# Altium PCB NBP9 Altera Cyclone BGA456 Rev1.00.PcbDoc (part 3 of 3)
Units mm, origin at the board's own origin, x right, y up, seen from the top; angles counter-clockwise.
Board outline 69 x 80.99 mm, 6 copper layers (Top Layer, MidLayer1, InternalPlane1, InternalPlane2, MidLayer2, Bottom Layer); 105 components, 269 nets, 899 pads, 453 vias.
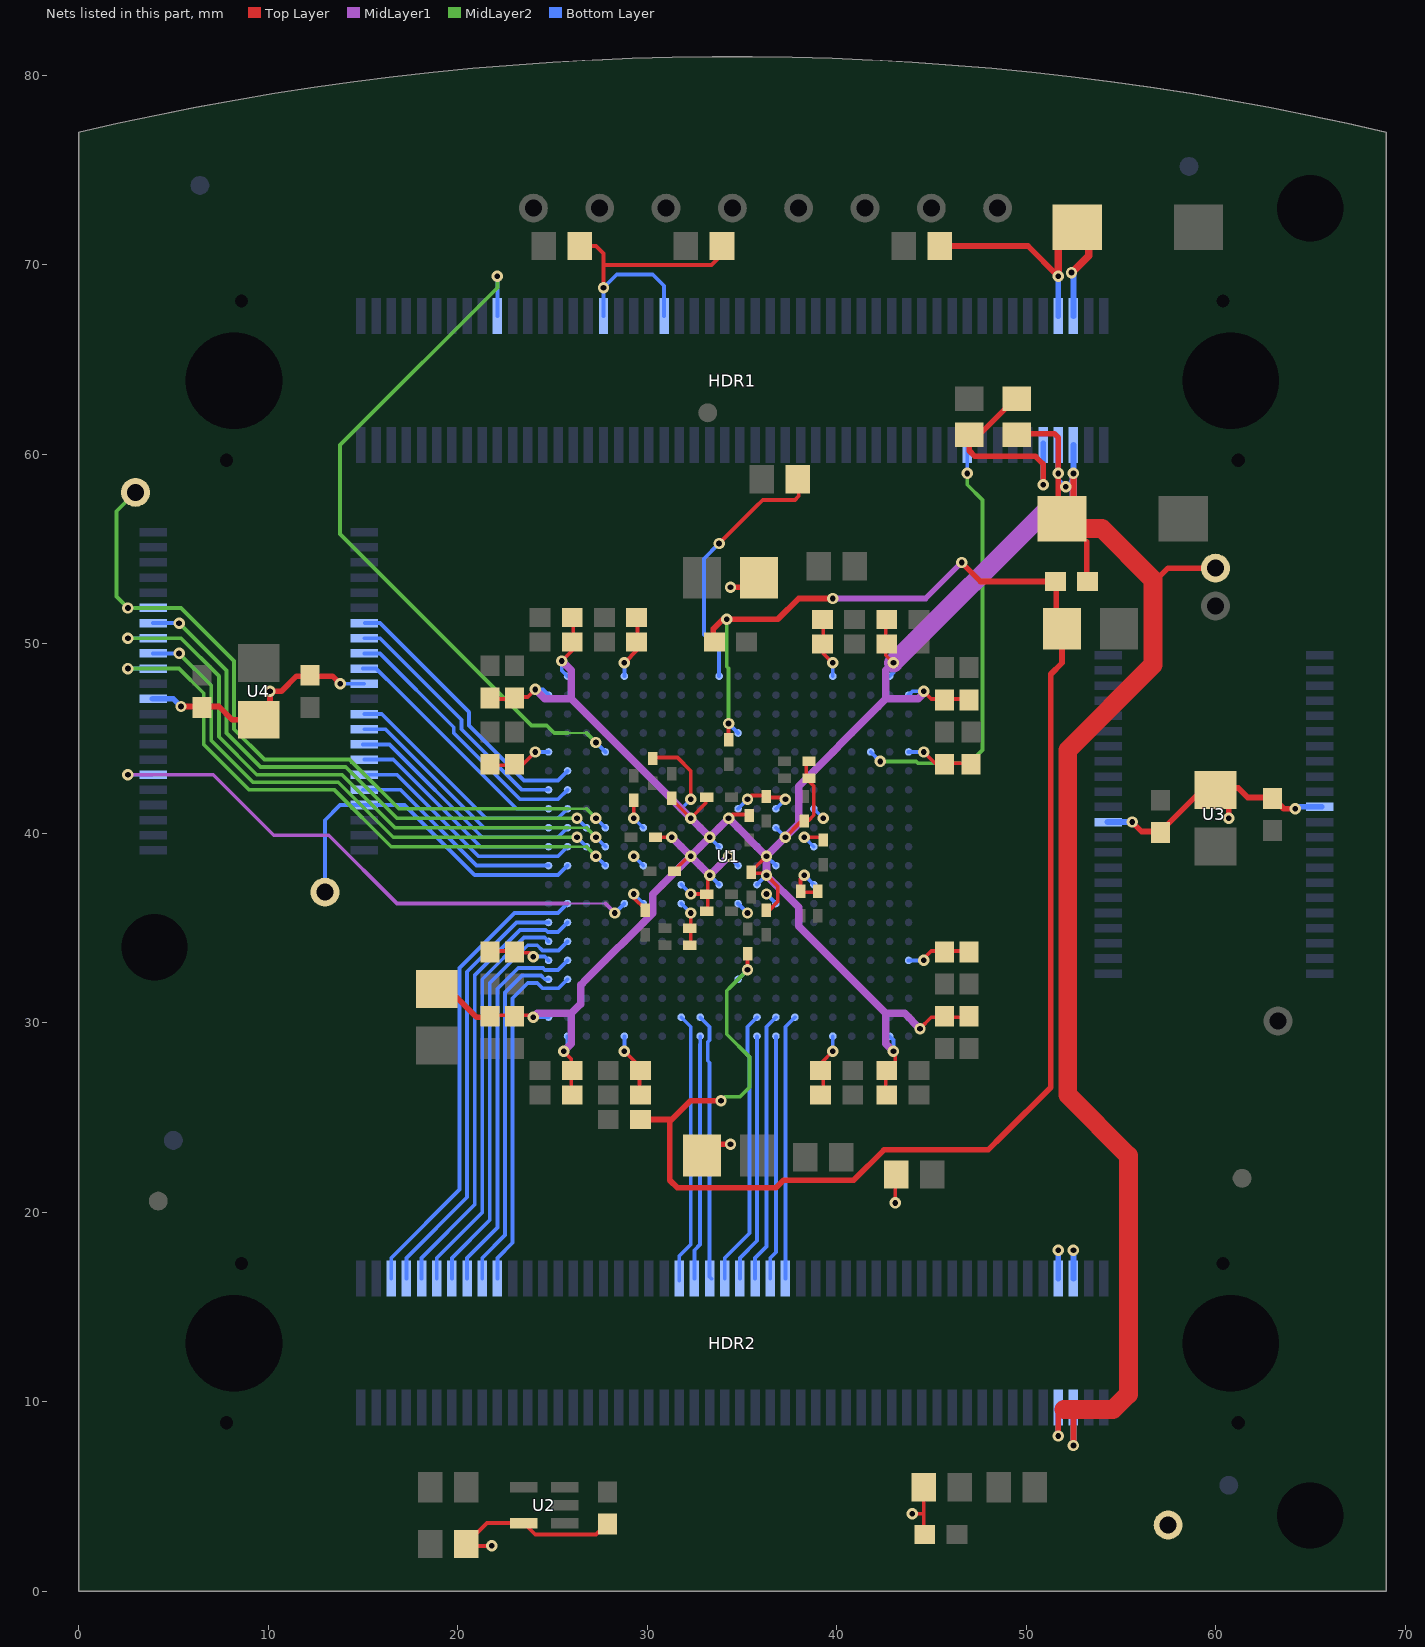
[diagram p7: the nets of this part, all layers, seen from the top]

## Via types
v1: diameter 0.6, hole 0.3, Top Layer to Bottom Layer, 453 vias

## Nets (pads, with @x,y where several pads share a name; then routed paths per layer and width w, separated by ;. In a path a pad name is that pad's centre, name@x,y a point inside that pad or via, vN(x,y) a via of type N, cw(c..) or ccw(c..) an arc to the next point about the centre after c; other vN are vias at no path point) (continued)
SRAM1_D4: U1.U10 U4.13 | length 32.4
  MidLayer2 w0.127: 25.8,39.3 26.8,39.3
  MidLayer2 w0.2: v1(2.6,48.7) 5.3,48.7 6.6,47.4 6.6,44.7 9,42.3 13.5,42.3 16.5,39.3 25.8,39.3 ; 26.8,39.3 v1(27.3,38.8)
  Bottom Layer w0.2: v1(2.6,48.7) U4.13@3.925,48.7 ; v1(27.3,38.8) U1.U10@27.8,38.3
SRAM1_D5: U1.V11 U4.14 | length 28.8
  MidLayer2 w0.2: v1(5.3,49.5) 7,47.8 7,44.9 9.2,42.7 13.7,42.7 16.6,39.8 v1(26.3,39.8)
  Bottom Layer w0.2: U4.14@3.925,49.5 v1(5.3,49.5) ; v1(26.3,39.8) U1.V11@26.8,39.3
SRAM1_D6: U1.U11 U4.15 | length 33.2
  MidLayer2 w0.127: 25.8,40.3 26.8,40.3
  MidLayer2 w0.2: v1(2.6,50.3) 5.4,50.3 7.4,48.3 7.4,45.1 9.4,43.1 13.9,43.1 16.7,40.3 25.8,40.3 ; 26.8,40.3 v1(27.3,39.8)
  Bottom Layer w0.2: v1(2.6,50.3) U4.15@3.9,50.3 ; v1@27.5,39.6 v1(27.3,39.8) U1.U11@27.8,39.3
SRAM1_D7: U1.V12 U4.16 | length 29.6
  MidLayer2 w0.2: v1(5.3,51.1) 7.8,48.6 7.8,45.3 9.6,43.5 14.1,43.5 16.8,40.8 v1(26.3,40.8)
  Bottom Layer w0.2: U4.16@3.925,51.1 v1(5.3,51.1) ; v1@26.5,40.6 v1(26.3,40.8) U1.V12@26.8,40.3
SRAM1_D8: U1.W15 U4.29 | length 14.8
  Bottom Layer w0.2: U4.29@15.1,51.1 15.9,51.1 20.6,46.4 20.6,45.7 23.5,42.8 25.3,42.8 U1.W15@25.8,43.3
SRAM1_D9: U1.Y14 U4.30 | length 13.3
  Bottom Layer w0.2: U4.30@15.075,50.3 15.9,50.3 20.2,46 20.2,45.5 23.4,42.3 24.375,42.3 ; 24.4,42.3 U1.Y14@24.8,42.3
SRAM1_D10: U1.W14 U4.31 | length 14.3
  Bottom Layer w0.2: U4.31@15.075,49.5 15.9,49.5 19.8,45.6 19.8,45.3 23.3,41.8 25.3,41.8 U1.W14@25.8,42.3
SRAM1_D11: U1.Y13 U4.32 | length 12.8
  Bottom Layer w0.2: U4.32@15,48.7 15.7,48.7 16.9,47.5 23.1,41.3 24.375,41.3 ; 24.4,41.3 U1.Y13@24.8,41.3
SRAM1_D12: U1.W13 U4.35 | length 13.2
  Bottom Layer w0.2: U4.35@15.075,46.3 16,46.3 21,41.3 21.5,40.8 25.3,40.8 25.499,41 U1.W13@25.8,41.3
SRAM1_D13: U1.Y12 U4.36 | length 11.9
  Bottom Layer w0.2: U4.36@15.075,45.5 16.2,45.5 21.4,40.3 24.375,40.3 ; 24.4,40.3 U1.Y12@24.8,40.3
SRAM1_D14: U1.W12 U4.37 | length 13
  Bottom Layer w0.2: U4.37@15,44.7 16.4,44.7 21.3,39.8 25.3,39.8 U1.W12@25.8,40.3
SRAM1_D15: U1.Y11 U4.38 | length 11.6
  Bottom Layer w0.2: U4.38@15.075,43.9 16.6,43.9 21.2,39.3 U1.Y11@24.8,39.3
SRAM1_E: U1.T8 U4.6 | length 30.7
  MidLayer1 w0.127: 25.8,36.3 27.8,36.3
  MidLayer1 w0.2: v1(2.6,43.1) 7.1,43.1 10.3,39.9 13.2,39.9 16.8,36.3 25.8,36.3 ; 27.8,36.3 v1(28.3,35.8)
  Bottom Layer w0.2: v1(2.6,43.1) U4.6@3.9,43.1 ; v1(28.3,35.8) U1.T8@28.8,36.3
SRAM1_LB: U1.W11 U4.39 | length 12.7
  Bottom Layer w0.2: U4.39@15.075,43.1 16.8,43.1 21.1,38.8 25.3,38.8 U1.W11@25.8,39.3
SRAM1_OE: TP2.1 U1.W10 U4.41 | length 18.7
  Bottom Layer w0.2: TP2.1@13,36.9 13,40.7 13.8,41.5 17.2,41.5 20.9,37.8 25.3,37.8 U1.W10@25.8,38.3
SRAM1_UB: U1.Y10 U4.40 | length 11.4
  Bottom Layer w0.2: U4.40@15,42.3 17,42.3 21,38.3 24.375,38.3 ; 24.4,38.3 U1.Y10@24.8,38.3
SRAM1_W: TP5.1 U1.U12 U4.17 | length 40.5
  MidLayer2 w0.127: 25.8,41.3 26.8,41.3
  MidLayer2 w0.2: TP5.1@3,58 2,57 2,52.5 v1(2.6,51.9) 5.4,51.9 8.2,49.1 8.2,45.5 9.8,43.9 14.3,43.9 16.9,41.3 25.8,41.3 ; 26.8,41.3 v1(27.3,40.8)
  Bottom Layer w0.2: v1(2.6,51.9) U4.17@3.9,51.9 ; v1@27.5,40.6 v1(27.3,40.8) U1.U12@27.8,40.3
SW0: HDR2.44 U1.N2 | length 14.4
  Bottom Layer w0.2: HDR2.44@31.7,16.4 31.7,17.7 32.3,18.3 32.3,29.8 U1.N2@31.8,30.3
SW1: HDR2.46 U1.M1 | length 13
  Bottom Layer w0.2: HDR2.46@32.5,16.5 32.5,18 32.8,18.3 32.8,28.875 ; 32.8,28.8 U1.M1@32.8,29.3
SW2: HDR2.48 U1.M2 | length 14.1
  Bottom Layer w0.2: U1.M2@32.8,30.3 33.3,29.8 33.3,29.1 33.2,29 33.2,28 33.3,27.9 33.3,16.6 33.35,16.55 HDR2.48@33.4,16.5
SW3: HDR2.50 U1.J2 | length 14.6
  Bottom Layer w0.2: HDR2.50@34.1,16.5 34.1,17.6 35.4,18.9 35.4,28.2 35.3,28.3 35.3,29.8 U1.J2@35.8,30.3
SW4: HDR2.52 U1.J1 | length 13.1
  Bottom Layer w0.2: HDR2.52@34.9,16.5 34.9,17.6 35.8,18.5 35.8,28.875 ; 35.8,28.9 U1.J1@35.8,29.3
SW5: HDR2.54 U1.H2 | length 14.3
  Bottom Layer w0.2: HDR2.54@35.7,16.5 35.7,17.6 36.3,18.2 36.3,29.8 U1.H2@36.8,30.3
SW6: HDR2.56 U1.H1 | length 13
  Bottom Layer w0.2: HDR2.56@36.5,16.5 36.5,17.6 36.8,17.9 36.8,28.875 ; 36.8,28.8 U1.H1@36.8,29.3
SW7: HDR2.58 U1.G2 | length 14
  Bottom Layer w0.2: HDR2.58@37.3,16.5 37.3,17.6 37.3,29.8 U1.G2@37.8,30.3
SWC0: HDR2.18 U1.Y4 | length 18.4
  Bottom Layer w0.2: HDR2.18@21.3,16.5 21.3,17.6 22.5,18.8 22.5,31.6 23.4,32.5 24.4,32.5 24.6,32.3 U1.Y4@24.8,32.3
SWC1: HDR2.16 U1.W5 | length 20.4
  Bottom Layer w0.2: HDR2.16@20.5,16.5 20.5,17.6 22.1,19.2 22.1,31.8 23.2,32.9 24.5,32.9 24.6,32.8 25.3,32.8 U1.W5@25.8,33.3
SWC2: HDR2.14 U1.W6 | length 21.7
  Bottom Layer w0.2: HDR2.14@19.7,16.5 19.7,17.6 21.7,19.6 21.7,32.1 23.7,34.1 24.2,34.1 24.475,33.825 25.325,33.825 U1.W6@25.8,34.3
SWC3: HDR2.6 U1.W8 | length 25
  Bottom Layer w0.2: HDR2.6@16.5,16.5 16.5,17.6 20.1,21.2 20.1,32.9 23,35.8 25.3,35.8 U1.W8@25.8,36.3
SWR0: HDR2.20 U1.W4 | length 18.7
  Bottom Layer w0.2: HDR2.20@22.1,16.5 22.1,17.6 22.9,18.4 22.9,31.3 23.7,32.1 24.2,32.1 24.475,31.825 25.325,31.825 U1.W4@25.8,32.3
SWR1: HDR2.12 U1.Y6 | length 21.3
  Bottom Layer w0.2: HDR2.12@18.9,16.5 18.9,17.6 21.3,20 21.3,32.3 23.5,34.5 24.6,34.5 U1.Y6@24.8,34.3
SWR2: HDR2.10 U1.W7 | length 23.3
  Bottom Layer w0.2: HDR2.10@18.1,16.5 18.1,17.6 20.9,20.4 20.9,32.5 23.3,34.9 24.656,34.9 24.756,34.8 25.3,34.8 U1.W7@25.8,35.3
SWR3: HDR2.8 U1.Y7 | length 22.9
  Bottom Layer w0.2: HDR2.8@17.3,16.5 17.3,17.6 20.5,20.8 20.5,32.7 23.1,35.3 24.375,35.3 ; 24.4,35.3 U1.Y7@24.8,35.3
TDO: R7.2 U1.L20 | length 15.7
  Top Layer w0.2: 35,56.5 v1(33.8,55.3) 35.7,57.2 36.1,57.6 37.8,57.6 38,57.8 R7.2@38,58.8
  Bottom Layer w0.2: U1.L20@33.8,48.3 33.8,49.7 33,50.5 33,54.5 v1(33.8,55.3) v1@33.8,55.4
TEST: HDR1.81 U1.C16 | length 23.2
  MidLayer2 w0.2: v1(42.3,43.8) 44.2,43.8 44.3,43.7 47,43.7 47.7,44.4 47.7,57.6 46.9,58.4 v1(46.9,59)
  Bottom Layer w0.2: U1.C16@41.8,44.3 v1(42.3,43.8) v1@42.101,43.999 ; v1(46.9,59) HDR1.81@46.9,60.5
VCC: C2.1 C3.1 C4.1 C5.1 C9.1 C10.1 C11.1 C12.1 C13.1 C14.1 C15.1 C16.1 C17.2 C28.1 C29.1 C30.1 C31.1 C32.1 C33.1 C34.1 C35.1 C36.1 C37.1 C38.1 C39.1 C40.1 C41.1 C42.1 C43.1 C44.1 C45.1 C46.1 C47.1 C48.1 C49.1 C51.1 HDR1.34 HDR1.42 HDR1.94 HDR1.96 HDR2.94 HDR2.96 R1.1 R2.1 R3.1 R10.1 R11.2 R12.2 TP3.1 U1.A5 U1.A16 U1.E1 U1.E20 U1.F9 U1.F11 U1.F13 U1.H8 U1.H13 U1.K8 U1.K13 U1.N8 U1.N13 U1.R8 U1.R10 U1.R12 U1.T1 U1.T20 U1.Y5 U1.Y16 U2.5 U3.11 U3.33 U4.11 U4.33 | length 133.1
  Top Layer w0.2: R11.2@20.45,2.5 21.55,3.6 U2.5@23.5,3.6 24.1,3 27.3,3 C17.2@27.9,3.6 ; R11.2@20.5,2.4 v1(21.8,2.4) ; C9.1@21.7,33.8 C34.1@23,33.8 ; C32.1@21.7,43.7 21.8,43.6 23,43.6 23.4,43.6 v1(24.1,44.3) ; C34.1@23,33.7 23.8,33.7 v1(24,33.5) ; R3.1@26.4,71 27.3,71 27.7,70.6 v1(27.7,68.8) ; 27.7,70 33.4,70 33.9,70.5 R2.1@33.9,71.1 ; v1@28.7,28.4 v1(28.8,28.5) 29.7,27.6 C41.1@29.7,27.5 ; v1@28.7,49.1 v1(28.8,49) 29.5,49.7 29.5,51.3 C15.1@29.2,51.6 ; v1(29.3,36.8) 29.3,36.6 C30.1@29.9,36 ; v1(29.3,40.8) C38.1@29.3,41.8 ; C37.1@29.6,26.2 C41.1@29.6,27.6 ; C31.1@30.2,44 31.6,44 32.3,43.3 v1(32.3,41.8) ; C13.1@32.3,34.1 v1(32.3,35.8) ; v1(35.3,41.8) 35.5,42 C36.1@36.3,42 ; C2.1@35.9,53.6 C2.1@36,53.6 ; C36.1@36.3,41.9 37.2,41.9 v1(37.3,41.8) ; v1(38.3,39.8) C44.1@39.3,39.8 ; v1@38.4,37.7 v1(38.3,37.8) 38.1,37.6 38.1,36.9 C47.1@39,36.9 ; C16.1@39.3,26.2 39.3,27.3 39.2,27.4 39.2,27.9 v1(39.8,28.5) v1@39.9,28.4 ; C33.1@39.3,50 39.3,49.5 v1(39.8,49) ; C33.1@39.3,50.1 C14.1@39.3,51.3 ; v1(43.1,20.5) R12.2@43.1,22 ; v1(44,4.1) 44.6,4.1 ; v1@44.5,33.3 45,33.8 C43.1@47,33.8 ; C29.1@44.6,2.9 R10.1@44.6,5.5 ; v1(44.6,44.3) 45.2,43.7 45.7,43.7 C11.1@47.1,43.7
  Top Layer w0.3: v1(5.4,46.7) 7.4,46.7 8.1,46 C4.1@9.5,46 10.1,46.6 v1(10.1,47.5) 10.7,47.5 11.5,48.3 13.4,48.3 v1(13.8,47.9) ; C3.1@32.8,23.6 v1(34.4,23.6) ; v1(34.4,53) 35.4,53 C2.1@35.9,53.5 ; R1.1@45.4,71 50.1,71 v1(51.7,69.4) ; v1(55.6,40.6) 56.1,40.1 57.1,40.1 59.4,42.4 61.2,42.4 61.7,41.9 63,41.9 63.6,41.3 v1(64.2,41.3) ; C5.1@60,42.4 60.7,41.7 v1(60.7,40.8)
  Top Layer w0.4: v1(51.7,69.4) 51.7,71.8 51.9,72 C51.1@53.3,72 ; v1(52.4,69.6) 53.3,70.5 C51.1@53.3,71.9
  Bottom Layer w0.2: v1(13.8,47.9) U4.33@15.075,47.9 ; v1(24,33.5) 24.6,33.5 U1.Y5@24.8,33.3 ; v1(24.1,44.3) U1.Y16@24.8,44.3 ; HDR1.34@27.7,67.3 v1(27.7,68.8) 28.4,69.5 30.3,69.5 30.9,68.9 HDR1.42@30.9,67.3 ; v1@28.8,28.6 U1.T1@28.8,29.3 ; U1.T20@28.8,48.3 v1(28.8,49) ; v1(29.3,36.8) U1.R8@29.8,36.3 ; v1(29.3,38.8) U1.R10@29.8,38.3 ; v1(29.3,40.8) U1.R12@29.8,40.3 ; U1.N8@31.8,36.3 v1(32.3,35.8) ; U1.N13@31.8,41.3 v1(32.3,41.8) ; U1.K13@34.8,41.3 v1(35.3,41.8) ; U1.K8@34.8,36.3 v1(35.3,35.8) ; v1(36.3,36.8) U1.H8@36.8,36.3 ; U1.H13@36.8,41.3 v1(37.3,41.8) ; v1(38.3,37.8) U1.F9@38.8,37.3 ; v1(38.3,39.8) U1.F11@38.8,39.3 ; U1.F13@38.8,41.3 v1(39.3,40.8) ; v1@39.8,28.6 U1.E1@39.8,29.3 ; U1.E20@39.8,48.3 v1(39.8,49) ; U1.A5@43.8,33.3 v1@44.5,33.3 ; U1.A16@43.8,44.3 v1(44.6,44.3)
  Bottom Layer w0.3: U4.11@3.9,47.1 5,47.1 v1(5.4,46.7) ; HDR2.94@51.7,16.5 v1(51.7,18) ; HDR1.94@51.7,67.3 v1(51.7,69.4) ; v1@52.4,69.5 v1(52.4,69.6) ; HDR2.96@52.5,16.5 v1(52.5,18) ; HDR1.96@52.5,67.3 v1@52.5,69.5 ; U3.11@54.3,40.6 v1(55.6,40.6) ; v1(64.2,41.3) 64.3,41.4 U3.33@65.6,41.4
  other v1: 44.6,33.3 51.7,69.4
VCCA_PLL1: C6.1 C52.1 C53.1 C54.1 C55.1 L1.2 U1.K4 U1.K17 | length 95.6
  Top Layer w0.2: C54.1@34.3,45 v1(34.3,45.8) ; v1(35.3,32.8) C55.1@35.3,33.6
  Top Layer w0.3: C53.1@29.65,24.9 31.3,24.9 ; C52.1@33.5,50 33.5,50.8 34,51.3 36.9,51.3 38,52.4 v1(39.8,52.4) ; v1(33.9,25.9) 32.3,25.9 31.2,24.8 31.2,21.7 31.6,21.3 36.8,21.3 37.2,21.7 40.9,21.7 42.5,23.3 48,23.3 48.8,24.1 51.3,26.6 51.3,48.4 51.9,49 C6.1@51.9,50.8 ; v1(46.6,54.3) 47.6,53.3 51.6,53.3 51.6,51.3 C6.1@52,50.9
  MidLayer1 w0.3: v1(39.8,52.4) 44.7,52.4 v1(46.6,54.3)
  MidLayer2 w0.2: v1(33.9,25.9) 34.1,26.1 34.9,26.1 35.4,26.6 35.4,28.2 34.2,29.4 34.2,31.7 34.4,31.9 v1(35.3,32.8) ; v1(34.2,51.3) 34.2,50.7 34.2,48.8 34.3,48.7 v1(34.3,45.8)
  Bottom Layer w0.2: v1(34.3,45.8) U1.K17@34.8,45.3 ; U1.K4@34.8,32.3 v1(35.3,32.8)
VCCINT: C1.1 C7.1 C8.1 C18.1 C19.1 C20.1 C21.1 C22.1 C23.1 C24.1 C25.1 C26.1 C27.1 C50.1 C56.1 C57.1 C58.1 C59.1 C60.1 C61.1 C62.1 C63.1 C64.1 C65.1 C66.1 C67.1 C68.1 C69.1 C70.1 C71.1 HDR1.93 HDR1.95 HDR2.93 HDR2.95 L1.1 R8.1 TP6.1 U1.A2 U1.A19 U1.B1 U1.B20 U1.H10 U1.H12 U1.J9 U1.J11 U1.K10 U1.K12 U1.L9 U1.L11 U1.M10 U1.M12 U1.N9 U1.N11 U1.W1 U1.W20 U1.Y2 U1.Y19 | length 224.5
  Top Layer w0.2: C63.1@21.7,30.4 23.9,30.4 v1(24,30.3) ; C58.1@21.7,47.2 21.8,47.1 C67.1@23,47.1 ; C67.1@23,47.2 23.7,47.2 v1(24.1,47.6) ; v1(25.5,49.1) 26.1,49.7 26.1,51.3 C59.1@25.9,51.5 ; v1(25.6,28.5) 26,28.1 C57.1@26,26.3 ; C21.1@30.4,39.8 v1(31.3,39.8) ; C8.1@31.3,41.9 31.3,41.8 v1(32.3,40.8) 33.1,41.6 C24.1@33.1,41.8 ; C27.1@31.4,38 32.2,38.8 v1(32.3,38.8) ; v1(32.3,36.8) C7.1@33.2,36.8 ; C23.1@33.2,35.9 C7.1@33.2,36.8 ; v1(33.3,37.8) 33.2,37.7 C7.1@33.2,36.8 ; v1(34.3,40.8) 34.5,41 C20.1@35.3,41 ; C26.1@35.5,37.9 36.2,37.9 v1(36.3,37.8) 36.9,37.2 36.9,36.4 36.4,35.9 C22.1@36.3,35.9 ; C26.1@35.5,38 v1(36.3,38.8) ; v1(37.3,39.8) 38.1,40.6 C18.1@38.3,40.6 ; C18.1@38.2,40.7 38.54,40.7 38.8,40.96 38.8,42.5 38.4,42.9 C19.1@38.4,43.8 ; C62.1@42.6,26.2 C65.1@42.6,27.6 ; C56.1@42.7,51.4 42.6,51.3 42.6,49.4 v1(43,49) ; v1(43,28.5) 43.1,28.4 C65.1@43.1,27.5 ; v1(44.4,29.7) 45,30.3 C61.1@47,30.3 ; v1(44.6,47.5) 45,47.1 C60.1@47,47.1
  Top Layer w0.3: C1.1@18.9,31.8 19.5,31.8 21,30.3 C63.1@21.7,30.3 ; R8.1@49.5,61.1 51.5,61.1 51.7,60.9 C50.1@51.7,56.6 ; v1(51.7,8.2) 51.7,9.6 ; v1(52.5,7.7) 52.5,9.6 ; C50.1@52.5,57.2 v1(52.5,59) ; L1.1@53.2,53.3 53.2,55.4 ; 56.6,53.1 57.5,54 TP6.1@60,54
  Top Layer w1: C50.1@51.9,56.1 54,56.1 56.7,53.4 56.7,48.9 52.2,44.4 52.2,26.2 55.4,23 55.4,13.8 ; 52,9.6 54.6,9.6 55.4,10.4 55.4,14
  MidLayer1 w0.2: 51.7,58.7 v1(51.7,59)
  MidLayer1 w0.4: v1(24,30.3) 24.2,30.5 26,30.5 ; v1(24.1,47.6) 24.6,47.1 26,47.1 ; v1(25.5,49.1) 26,48.6 26,47.1 ; v1(25.6,28.5) 26,28.9 26,30.5 ; v1(31.3,39.8) v1(32.3,38.8) ; v1(34.3,38.8) v1(33.3,37.8) v1(32.3,38.8) ; v1(43,28.5) 42.6,28.9 42.6,30.5 ; v1(43,49) 42.6,48.6 42.6,47.1 ; v1(44.4,29.7) 43.6,30.5 42.6,30.5 ; v1@44.65,47.45 44.3,47.1 42.6,47.1 ; 52.5,57.3 v1(52.5,59) ; 26,30.5 26.5,31 26.5,32 26.8,32.3 30.3,35.8 30.3,36.8 v1(32.3,38.8) ; 26,47.1 v1(33.3,39.8) ; v1(32.3,38.8) v1(33.3,39.8) ; v1(33.3,39.8) v1(34.3,40.8) v1(36.3,38.8) ; v1(36.3,38.8) v1(36.3,37.8) 38,36.1 38,35.1 42.6,30.5 ; v1(36.3,38.8) v1(37.3,39.8) 38,40.5 38,42.5 42.2,46.7 42.6,47.1
  MidLayer1 w1: v1(43,49) 51.3,57.3 52.5,57.3
  Bottom Layer w0.2: v1(24,30.3) U1.Y2@24.8,30.3 ; v1(24.1,47.6) 24.5,47.6 U1.Y19@24.8,47.3 ; v1(25.5,49.1) 25.5,48.6 U1.W20@25.8,48.3 ; v1@25.65,28.45 25.8,28.6 U1.W1@25.8,29.3 ; v1(31.3,39.8) U1.N11@31.8,39.3 ; U1.N9@31.8,37.3 v1(32.3,36.8) ; v1(32.3,38.8) U1.M10@32.8,38.3 ; v1(32.3,40.8) U1.M12@32.8,40.3 ; v1(33.3,37.8) U1.L9@33.8,37.3 ; v1(33.3,39.8) U1.L11@33.8,39.3 ; v1(34.3,38.8) U1.K10@34.8,38.3 ; v1(34.3,40.8) U1.K12@34.8,40.3 ; U1.J9@35.8,37.3 v1(36.3,37.8) ; U1.J11@35.8,39.3 v1(36.3,38.8) U1.H10@36.8,38.3 ; U1.H12@36.8,40.3 v1(37.3,39.8) ; U1.B1@42.8,29.3 43,29.1 v1(43,28.5) ; U1.B20@42.8,48.3 43,48.5 v1(43,49) ; U1.A2@43.8,30.3 v1(44.4,29.7) ; U1.A19@43.8,47.3 44,47.5 v1(44.6,47.5) ; v1(51.7,59) 51.7,58.7 v1(52.1,58.3) 52.5,58.7 v1(52.5,59)
  Bottom Layer w0.3: v1(51.7,8.2) HDR2.93@51.7,9.7 ; v1(51.7,59) HDR1.93@51.7,60.5 ; v1(52.5,7.7) HDR2.95@52.5,9.7 ; v1(52.5,59) HDR1.95@52.5,60.5
VDRIVE: HDR1.20 U1.U16 | length 38.2
  MidLayer2 w0.127: 25.8,45.3 26.8,45.3
  MidLayer2 w0.2: v1(22.1,69.4) 22.1,68.8 14.3,61 13.8,60.5 13.8,55.8 23.9,45.7 24.7,45.7 25.1,45.3 25.8,45.3 ; 26.8,45.3 v1(27.3,44.8)
  Bottom Layer w0.2: HDR1.20@22.1,67.3 v1(22.1,69.4) ; v1@27.5,44.6 v1(27.3,44.8) U1.U16@27.8,44.3
VREF: HDR1.91 R8.2 R9.1 | length 11.7
  Top Layer w0.3: R8.2@49.5,63 49.475,62.975 47.6,61.1 47,61.1 47,60.2 47.3,59.9 50.5,59.9 50.9,59.5 v1(50.9,58.4)
  Bottom Layer w0.3: v1(50.9,58.4) HDR1.91@50.9,60.6
pads on no net: HDR1.MH1 HDR1.MH2 HDR1.MH3 HDR1.MH4 HDR1.MH5 HDR1.MH6 HDR2.MH1 HDR2.MH2 HDR2.MH3 HDR2.MH4 HDR2.MH5 HDR2.MH6 U1.B3 U1.C4 U1.C6 U1.D3 U1.D17 U1.D18 U1.E12 U1.E16 U1.F6 U1.F8 U1.F10 U1.F12 U1.F14 U1.F15 U1.G7 U1.G14 U1.G15 U1.H7 U1.H14 U1.H15 U1.J6 U1.J7 U1.J8 U1.J13 U1.J14 U1.J16 U1.K2 U1.K15 U1.K16 U1.K19 U1.L2 U1.L4 U1.L8 U1.L13 U1.M6 U1.M7 U1.M8 U1.M13 U1.M14 U1.M15 U1.N6 U1.N7 U1.N14 U1.N15 U1.P6 U1.P7 U1.P14 U1.P15 U1.P16 U1.R7 U1.R9 U1.R11 U1.R13 U1.R14 U1.R15 U1.R16 U1.V14 U2.1

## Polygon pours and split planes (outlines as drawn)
GND on Top Layer "Top Layer-GND" (solid, remove dead copper, pour order 1000): 0,0 0,82.9 69,82.9 69,0
VCCINT on MidLayer1 "MidLayer1-VCCINT" (solid, remove dead copper, pour order 1001): 0,0 0,82.7 69,82.7 69,0.1 0,0.1
VCC on MidLayer2 "MidLayer2-VCC" (solid, remove dead copper, pour order 1002): 0,0 0,83.4 69,83.4 69,0
GND on Bottom Layer "Bottom Layer-GND" (solid, remove dead copper, pour order 1003): 0,0 0,83.2 69,83.2 69,0
VCC on InternalPlane1 (split plane): 36.232,80.189 37.965,80.159 39.696,80.109 41.427,80.039 43.158,79.949 44.887,79.839 46.614,79.709 48.34,79.559 50.064,79.389 51.786,79.2 53.506,78.99 55.223,78.761 56.938,78.511 58.649,78.242 60.358,77.953 62.062,77.645 63.763,77.317 65.461,76.969 67.154,76.602 68.197,76.363 68.197,0.803 0.803,0.803 0.803,76.363 1.846,76.602 3.539,76.969 5.237,77.317 6.938,77.645 8.642,77.953 10.351,78.242 12.062,78.511 13.777,78.761 15.494,78.99 17.214,79.2 18.936,79.389 20.66,79.559 22.386,79.709 24.113,79.839 25.842,79.949 27.573,80.039 29.304,80.109 31.035,80.159 32.768,80.189 34.5,80.199
GND on InternalPlane2 (split plane): 36.232,80.189 37.965,80.159 39.696,80.109 41.427,80.039 43.158,79.949 44.887,79.839 46.614,79.709 48.34,79.559 50.064,79.389 51.786,79.2 53.506,78.99 55.223,78.761 56.938,78.511 58.649,78.242 60.358,77.953 62.062,77.645 63.763,77.317 65.461,76.969 67.154,76.602 68.197,76.363 68.197,0.803 0.803,0.803 0.803,76.363 1.846,76.602 3.539,76.969 5.237,77.317 6.938,77.645 8.642,77.953 10.351,78.242 12.062,78.511 13.777,78.761 15.494,78.99 17.214,79.2 18.936,79.389 20.66,79.559 22.386,79.709 24.113,79.839 25.842,79.949 27.573,80.039 29.304,80.109 31.035,80.159 32.768,80.189 34.5,80.199

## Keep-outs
Top Layer:
  circle w0.254: c4.2,20.6 r2.5
  circle w0.254: c33.2,62.2 r2.5
  circle w0.254: c61.4,21.8 r2.5
Bottom Layer:
  circle w0.254: c5,23.8 r2.5
  circle w0.254: c58.6,75.2 r2.5
  circle w0.254: c6.4,74.2 r2.5
  circle w0.254: c60.7,5.6 r2.5
Keep-Out Layer:
  the board outline again, w1.8

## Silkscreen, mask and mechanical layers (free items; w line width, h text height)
Top Overlay:
  circle w0.127: c4,34 r2.5
  circle w0.127: c65,4 r2.5
  circle w0.127: c65,73 r2.5
  lines w0.08: 20,27.1 21.4,28 ; 21.5,50.5 23,49.6 ; 22.7,27.4 22.7,28 ; 22.7,51.8 23.7,50.4 ; 23.2,25.4 23.6,25.8 23.6,27.6 23.8,27.6 ; 25.5,37.3 32.4,37.3 ; 26.1,38.3 29.7,38 ; 26.1,39.4 28.5,39.4 28.8,39.6 ; 26.2,42.3 29.1,42.3 ; 29.8,30.7 29.8,34.2 ; 29.9,23.2 29.9,24.3 ; 30.8,30.6 30.7,33.4 31.6,33.9 31.6,35.4 32.1,35.8 ; 31.8,30.6 31.8,33.8 31.9,33.9 ; 33,42.5 33.2,42.2 ; 33.1,35 33.7,34.6 33.7,30 ; 33.2,46.9 33.8,45.9 ; 33.2,51.3 33.8,50.7 ; 34.8,46.9 34.9,41.6 35.2,41.2 ; 35.6,33.8 35.8,33.7 35.8,30.6 ; 35.8,46.9 35.8,42.6 36,42.2 ; 36.5,35.5 37.4,35.2 ; 38.1,36.6 38.2,36.3 42.5,36.2 ; 38.5,41.3 42.6,41.3 ; 39.4,37.2 42.5,37.4 ; 39.5,43 39.9,43.3 42.5,43.3 ; 39.6,39.3 42.6,39.3 ; 44.9,50 46.6,51.1 ; 45,27.4 45.9,26.6 ; 45.7,49.6 46.2,50 47.4,50.2 ; 45.9,28 47.1,27.4 ; 46.1,63.4 46.1,64 ; 55.8,74.4 55.82,75.12 ; 57.9,2.6 58.8,1.7 61.5,1.7
  lines w0.127: 0,1.5 1.5,1.5 1.5,0 ; 0,22.3 1.5,22.3 1.5,23.4 0,23.4 ; 0.001,53.6 1.501,53.6 1.501,54.7 0.001,54.7 ; 0,75.5 1.5,75.5 1.5,77.3 ; 15.7,79.8 15.7,78.1 17,78.1 17,79.9 ; 49.7,80.2 49.7,78.7 51,78.7 51,80.1 ; 67.5,0 67.5,1.5 69,1.5 ; 67.5,77.3 67.5,75.5 69,75.5 ; 68.999,22.3 67.5,22.3 67.5,23.4 69,23.4
Bottom Overlay:
  drawing of 856 lines, arcs and shapes, not listed
  text "REV 1.00" at 47.8,76.5 h1.3
  text "NBP9" at 54.5,76.5 h1.3
  text "TP10" at 25.3,71.2 h0.8
  text "TP12" at 28.9,71.2 h0.8
  text "TP9" at 31.9,71.2 h0.8
  text "TP8" at 35.5,71.2 h0.8
  text "TP7" at 39.1,71.2 h0.8
  text "TP14" at 42.8,71.2 h0.8
  text "TP13" at 46.5,71.2 h0.8
  text "TP11" at 49.8,71.2 h0.8
  text "TP5" at 4.1,59.1 h0.8
  text "1" at 14.4,58.4 h1
  text "TP6" at 63.4,53.6 h0.8
  text "TP4" at 59,51.6 h0.8
  text "TP2" at 14.2,34.9 h0.8
  text "TP1" at 62.1,29.7 h0.8
  text "1" at 14.224,7.62 h1
  text "TP3" at 55.9,3.1 h0.8
PCB Boundary:
  the board outline again, w0.25
  text "PCB boundary coincides with centre-line of tracks and arc" at 0,-12 h0.75
Gerber ID:
  text ".Layer_Name" at 0,-6 h0.75
Printout ID:
  text ".Printout_Name" at 0,-10 h0.75
Design Information:
  drawing of 719 lines, arcs and shapes, not listed
  text "NBP9 REV 1.00" at 317.627,202.041 h1.27
  text "DESIGN INFORMATION" at 261.62,201.914 h1.52
  text "BOARD NAME:" at 299.212,201.914 h1.52
  text "BOARD TECHNOLOGY" at 261.62,199.374 h1.52
  text "BOARD SIZE (REFER ALSO PROFILING INFORMATION)" at 309.88,199.374 h1.27
  text "69.00mm" at 312.6,197.1 h1.52
  text "15.748" at 277.419,197.012 h1.52
  text "81.00mm" at 335.6,197 h1.52
  text "5.000" at 291.389,196.885 h1.52
  text "5" at 266.446,196.834 h1.52
  text "X" at 328.549,196.326 h1.78
  text "(MIN. TRACK/   PADS  /   CLEARANCE     IN 0.001'')" at 260.096,194.294 h1.27
  text "MINIMUM ANNULAR RING 0.05MM (0.002'') EXTERNAL PER IPC-2221 CLASS 3 LEVEL C AND IS THE" at 261.62,191.754 h1.27
  text "MANUFACTURING REGISTRATION ALLOWANCE" at 261.62,189.468 h1.27
  text "LAND SIZE CALCULATION MINIMUM - NOMINAL HOLE SIZE + 0.508MM (0.020'')" at 261.62,186.674 h1.27
  text "AS INSTRUCTED" at 347.65,182.28 h1.52
  text "X" at 299.263,182.153 h1.52
  text "CIRCUIT TYPE:" at 261.62,182.102 h1.52
  text "SS" at 284.48,182.102 h1.27
  text "DS" at 302.26,182.102 h1.27
  text "X" at 316.865,182.102 h1.52
  text "PTH" at 320.04,182.102 h1.27
  text "ML" at 330.962,182.102 h1.27
  text "X" at 334.772,182.102 h1.52
  text "No. OFF" at 337.82,182.102 h1.27
  text "FINGER CONNECTOR DIM PER:" at 261.62,179.054 h1.52
  text "AS SHOWN" at 337.82,179.054 h1.27
  text "No. OFF TOTAL" at 278.384,176.26 h1.52
  text "ONE SIDE" at 320.04,176.26 h1.27
  text "BOTH SIDES" at 337.82,176.006 h1.27
  text "VIAS:" at 261.62,173.339 h1.52
  text "NONE" at 273.05,173.339 h1.14
  text "X" at 281.432,173.339 h1.52
  text "FEED THRU'" at 284.48,173.339 h1.14
  text "X" at 299.212,173.339 h1.52
  text "TENTED" at 302.26,173.339 h1.14
  text "BURIED LAYER SEQUENCE" at 320.04,173.339 h1.14
  text "UNIQUE DRILL" at 284.48,170.291 h1.14
  text "2 SIZE" at 302.26,170.291 h1.14
  text "BLIND LAYER SEQUENCE" at 320.04,170.291 h1.14
  text "Layer Stack Manager (Protel)" at 297.053,168.005 h1.27
  text "X" at 334.772,168.005 h1.52
  text "AS SHOWN" at 337.82,168.005 h1.27
  text "LAYER CONSTRUCTION PER:" at 261.62,167.878 h1.52
  text "Protel" at 342.646,165.338 h1.27
  text "(PFW)" at 352.933,165.211 h1.27
  text "ARTWORK:" at 261.62,165.084 h1.52
  text "MANUAL" at 284.48,165.084 h1.27
  text "DIGITISED" at 302.26,165.084 h1.27
  text "X" at 316.992,165.084 h1.52
  text "CAD" at 320.04,165.084 h1.27
  text "TYPE" at 330.962,165.084 h1.27
  text "ARTWORK/PATTERN MASTER LIST" at 261.62,160.385 h1.52
  text "DESCRIPTION" at 262.89,157.972 h1.27
  text "DRAWING No./CAD FILE REF." at 281.559,157.972 h1.27
  text "LAYER NAME" at 322.834,157.972 h1.27
  text "GERBER FILE REF" at 343.586,157.896 h1.27
  text "PCB FILE" at 261.366,155.432 h1.27
  text "SpartanIIIBGA456" at 281.737,155.356 h1.27
  text "PcbDoc" at 312.979,155.356 h1.02
  text "Top Paste Mask" at 321.158,152.892 h1.02
  text "GTP" at 363.779,152.816 h1.27
  text "GERBER FILE" at 261.366,152.765 h1.27
  text "GTO" at 363.728,150.327 h1.27
  text "Top Overlay" at 321.158,150.301 h1.02
  text "GERBER FILE" at 261.366,150.225 h1.27
  text "Top Solder Mask" at 321.158,147.863 h1.02
  text "GTS" at 363.779,147.736 h1.27
  text "GERBER FILE" at 261.366,147.685 h1.27
  text "TOP LAYER" at 321.158,145.272 h1.02
  text "GTL" at 363.779,145.196 h1.27
  text "GERBER FILE" at 261.366,145.145 h1.27
  text "G1" at 363.728,142.834 h1.27
  text "MIDLAYER1" at 321.158,142.732 h1.02
  text "GERBER FILE" at 261.366,142.605 h1.27
  text "INTERNALPLANE1" at 321.158,140.192 h1.02
  text "GP1" at 363.779,140.116 h1.27
  text "GERBER FILE" at 261.366,140.065 h1.27
  text "INTERNALPLANE2" at 321.158,137.652 h1.02
  text "GP2" at 363.728,137.627 h1.27
  text "GERBER FILE" at 261.366,137.525 h1.27
  text "MIDLAYER2" at 321.158,135.112 h1.02
  text "G2" at 363.728,135.087 h1.27
  text "GERBER FILE" at 261.366,134.985 h1.27
  text "BOTTOMLAYER" at 321.158,132.572 h1.02
  text "GBL" at 363.779,132.496 h1.27
  text "GERBER FILE" at 261.366,132.445 h1.27
  text "Bottom Solder Mask" at 321.158,130.083 h1.02
  text "GBS" at 363.779,129.956 h1.27
  text "GERBER FILE" at 261.366,129.905 h1.27
  text "Bottom Overlay" at 321.158,127.492 h1.02
  text "GBO" at 363.779,127.416 h1.27
  text "GERBER FILE" at 261.366,127.365 h1.27
  text "Bottom Paste Mask" at 321.158,125.003 h1.02
  text "GBP" at 363.779,124.876 h1.27
  text "GERBER FILE" at 261.366,124.825 h1.27
  text "PCB Boundary" at 321.158,122.412 h1.02
  text "GM1" at 363.779,122.336 h1.27
  text "GERBER FILE" at 261.366,122.285 h1.27
  text "APERTURE LIST" at 261.366,119.872 h1.27
  text "APR" at 313.979,119.796 h1.27
  text "DRILL REPORT" at 261.366,117.332 h1.27
  text "DRR" at 313.979,117.256 h1.27
  text "EXCELLON DRILL" at 261.366,114.792 h1.27
  text "TXT" at 313.979,114.716 h1.27
  text "MATERIAL:" at 261.62,99.298 h1.52
  text "GLASS FIBRE EPOXY RESIN NEMA GRADE FR4 (MIL-S-13949H)" at 287.274,99.044 h1.27
  text "X" at 284.607,98.917 h1.52
  text "THICKNESS:" at 269.494,96.123 h1.27
  text "0.8mm" at 287.274,96.123 h1.27
  text "1.2mm" at 304.927,96.123 h1.27
  text "1.6mm" at 322.58,96.123 h1.27
  text "2.4mm" at 340.36,96.123 h1.27
  text "3.2mm" at 358.14,96.123 h1.27
  text "X" at 320.167,95.996 h1.52
  text "TOLERANCE:" at 269.367,93.075 h1.27
  text "IN A/W IPC-D-300G CLASS" at 287.02,93.075 h1.27
  text "3 LEVEL B" at 321.945,93.075 h1.27
  text "OTHER +/-" at 340.36,93.075 h1.27
  text "X" at 284.607,92.948 h1.52
  text "BOW & TWIST:" at 266.954,90.027 h1.27
  text "IN A/W IPC-D-300G CLASS" at 287.02,90.027 h1.27
  text "3 LEVEL B" at 321.945,90.027 h1.27
  text "AS SHOWN" at 340.487,89.9 h1.27
  text "X" at 284.607,89.773 h1.52
  text "COPPER THICKNESS (FINISHED)" at 269.367,86.725 h1.27
  text "OUTER:" at 274.193,84.439 h1.27
  text "18um" at 287.274,84.439 h1.27
  text "35um" at 314.325,84.439 h1.27
  text "70um" at 340.614,84.439 h1.27
  text "X" at 311.582,84.236 h1.52
  text "INNER SIGNAL:" at 265.811,81.391 h1.27
  text "18um" at 287.274,81.391 h1.27
  text "35um" at 314.325,81.391 h1.27
  text "70um" at 340.614,81.391 h1.27
  text "X" at 311.531,81.188 h1.52
  text "INNER PWR:" at 269.494,78.343 h1.27
  text "18um" at 287.274,78.343 h1.27
  text "35um" at 314.325,78.343 h1.27
  text "70um" at 340.614,78.343 h1.27
  text "X" at 311.658,78.216 h1.52
  text "STRUCTURE:" at 261.62,75.295 h1.52
  text "REFER" at 287.274,75.295 h1.27
  text "AS PER DRAWING No." at 287.147,72.12 h1.27
  text "AS SHOWN" at 340.487,72.12 h1.27
  text "X" at 337.947,71.993 h1.52
  text "DRILLING:" at 261.62,69.326 h1.52
  text "VIEWED FROM:" at 266.573,67.04 h1.27
  text "COMPONENT SIDE" at 287.274,67.04 h1.14
  text "SOLDER SIDE" at 314.071,67.04 h1.14
  text "X" at 284.607,66.786 h1.52
  text "REFERENCE:" at 268.859,63.992 h1.27
  text "AS SHOWN" at 287.147,63.865 h1.14
  text "PATTERN MASTER LIST" at 314.198,63.865 h1.14
  text "X" at 337.947,63.865 h1.52
  text "NC_DRILL FILES" at 340.487,63.865 h1.14
  text "X" at 284.607,63.738 h1.52
  text "PTH MINIMUM COPPER THICKNESS:" at 274.701,60.944 h1.27
  text "20um" at 314.325,60.944 h1.27
  text "X" at 311.658,60.817 h1.52
  text "OTHER" at 340.487,60.817 h1.27
  text "NPTH:" at 275.209,57.896 h1.27
  text "TENTED" at 287.147,57.769 h1.14
  text "X" at 311.658,57.769 h1.52
  text "PADS REMOVED" at 314.198,57.769 h1.14
  text "REMOVE PADS" at 340.487,57.769 h1.14
  text "X" at 284.607,57.642 h1.52
  text "2nd DRILL" at 287.147,54.721 h1.14
  text "BOTH" at 314.198,54.721 h1.14
  text "AS SHOWN" at 326.517,54.721 h1.14
  text "NONE" at 340.487,54.721 h1.14
  text "BOARD FINISH:" at 261.62,51.8 h1.52
  text "X" at 284.607,51.673 h1.52
  text "ETCHING" at 287.147,51.673 h1.14
  text "REFER PATTERN MASTER LIST" at 314.198,51.673 h1.14
  text "LEGEND / SCREEN PRINT:" at 281.94,48.752 h1.27
  text "NONE" at 314.198,48.625 h1.14
  text "COMPONENT" at 326.517,48.625 h1.14
  text "SOLDER" at 340.487,48.625 h1.14
  text "X" at 323.977,48.498 h1.52
  text "X" at 337.947,48.498 h1.52
  text "COLOUR:" at 272.161,45.704 h1.27
  text "WHITE" at 287.147,45.577 h1.14
  text "YELLOW" at 314.198,45.577 h1.14
  text "OTHER" at 340.487,45.577 h1.14
  text "X" at 284.607,45.45 h1.52
  text "X" at 284.607,42.529 h1.52
  text "LIQUID PHOTOIMAGEABLE" at 287.147,42.529 h1.14
  text "SCREEN PRINT" at 326.517,42.529 h1.14
  text "MATTE" at 287.147,39.481 h1.14
  text "GLOSS" at 299.847,39.481 h1.14
  text "GREEN" at 314.198,39.481 h1.14
  text "BLUE" at 326.517,39.481 h1.14
  text "G/Y" at 340.487,39.481 h1.14
  text "OTHER" at 351.917,39.481 h1.14
  text "X" at 297.18,39.354 h1.52
  text "SOLDER MASK COLOUR:" at 261.62,36.56 h1.14
  text "BLACK" at 287.147,36.433 h1.14
  text "GREEN" at 299.847,36.433 h1.14
  text "YELLOW" at 314.198,36.433 h1.14
  text "BLUE" at 326.517,36.433 h1.14
  text "OTHER" at 340.487,36.433 h1.14
  text "X" at 284.48,36.306 h1.52
  text "TRACK FINISH:" at 261.62,33.512 h1.52
  text "X" at 284.607,33.385 h1.52
  text "SELECTIVE SOLDER (HASL)" at 287.147,33.385 h1.14
  text "REFLOW SOLDER" at 326.517,33.385 h1.14
  text "SELECTIVE GOLD" at 287.147,30.337 h1.14
  text "um  (AREA" at 314.198,30.337 h1.14
  text "sq. mm)" at 342.011,30.337 h1.14
  text "REFER PATTERN MASTER LIST" at 287.147,27.289 h1.14
  text "OTHER" at 326.517,27.289 h1.14
  text "EDGE BOARD" at 261.62,24.368 h1.52
  text "1.3um HARD GOLD OVER 5um     NICKEL / TIN-NICKEL" at 287.147,24.241 h1.14
  text "CONTACTS:" at 261.62,22.209 h1.52
  text "HARD FINISH GOLDE PLATE" at 287.147,21.193 h1.14
  text "OTHER" at 326.517,21.193 h1.14
  text "AS SHOWN" at 287.147,18.145 h1.14
  text "REFER" at 326.517,18.145 h1.14
  text "PROFILING:" at 261.62,15.097 h1.52
  text "AS DIMENSIONED, MEASURED AND CUT FROM SPECIFIED DATUM." at 287.147,15.097 h1.14
  text "X" at 284.607,14.97 h1.52
  text "REFER PCB BLANK DWG No." at 287.274,12.176 h1.27
  text "USE PROFILE / ROUTE TAPE SUPPLIED (REFER PATTERN MASTER LIST)" at 287.274,9.128 h1.27
  text "SQUARE CUT" at 287.274,6.08 h1.27
  text "N.C. ROUTE" at 305.054,6.08 h1.27
  text "V. SCORE" at 322.834,6.08 h1.27
  text "BLANK" at 340.614,6.08 h1.27
  text "ACCEPTABILITY:" at 261.62,3.413 h1.52
  text "MATERIALS AND WORKMANSHIP FOR ALL PRINTED WIRING BOARDS TO MEET" at 283.845,3.286 h1.27
  text "OR EXCEED THE REQUIREMENTS OF:" at 283.845,0.492 h1.27
  text "IPC-6011/12 AND IPC-A-600E" at 287.401,-2.175 h1.27
  text "1" at 322.961,-2.175 h1.27
  text "2" at 331.851,-2.175 h1.27
  text "X" at 329.184,-2.302 h1.52
  text "X" at 284.734,-2.429 h1.52
  text "3" at 340.741,-4.334 h1.27
  text "UL CERTIFICATION" at 287.401,-5.223 h1.27
  text "AUSTEL" at 322.961,-5.223 h1.27
  text "X" at 284.734,-5.35 h1.52
  text "ML-P-55110F GRP" at 286.893,-8.271 h1.02
  text "A" at 305.181,-8.271 h1.27
  text "B" at 314.071,-8.271 h1.27
  text "AS2546" at 322.961,-8.271 h1.27
  text "OTHER" at 340.741,-8.271 h1.27
  text "ADDITIONAL" at 261.62,-11.192 h1.52
  text "NONE" at 287.401,-11.446 h1.27
  text "SAMPLE PLAN" at 305.181,-11.446 h1.27
  text "MIL-P-55110E SERIAL Nos. PER ORDER" at 322.961,-11.446 h1.27
  text "REQUIREMENTS:" at 261.62,-13.605 h1.52
  text "NONE" at 287.401,-14.494 h1.27
  text "ML-P-55110F GRP" at 304.673,-14.494 h1.02
  text "A" at 322.961,-14.494 h1.27
  text "B" at 331.851,-14.494 h1.27
  text "IPC CLASS:" at 337.82,-14.494 h1.27
  text "1" at 353.314,-14.494 h1.27
  text "2" at 359.664,-14.494 h1.27
  text "3" at 366.014,-14.494 h1.27
  text "QUALITY RELEASE REPORT" at 305.181,-17.542 h1.27
  text "OTHER" at 345.694,-17.542 h1.27
  text "PER ORDER" at 354.203,-17.669 h1.27
  text "X" at 343.027,-17.796 h1.52
  text "NONE" at 305.181,-20.59 h1.27
  text "REQUIRED" at 322.961,-20.59 h1.27
  text "PER ORDER" at 345.821,-20.59 h1.27
  text "ELECTRICAL TEST:" at 261.62,-20.717 h1.52
  text "X" at 320.294,-20.717 h1.52
  text "NONE" at 305.181,-23.638 h1.27
  text "1 SIDE" at 322.834,-23.638 h1.14
  text "2 SIDES" at 334.01,-23.638 h1.14
  text "MIN. PITCH" at 345.694,-23.638 h1.27
  text "0.65mm" at 359.283,-23.638 h1.27
  text "SURFACE MOUNT:" at 261.62,-23.765 h1.52
  text "X" at 331.775,-23.841 h1.52
  text "NONE" at 305.181,-26.686 h1.27
  text "FOIL" at 322.961,-26.686 h1.27
  text "LEGEND" at 334.391,-26.686 h1.27
  text "REFER" at 345.694,-26.686 h1.27
  text "MANUFACTURER'S ID/LOGO:" at 261.62,-26.813 h1.52
  text "X" at 302.514,-26.94 h1.52
  text "ISO9001/AS3901" at 308.991,-29.734 h1.27
  text "NONE" at 345.694,-29.734 h1.27
  text "MANUFACTURER'S ACCREDITATION:" at 261.62,-29.861 h1.52
  text "X" at 306.324,-29.861 h1.52
  text "PER ORDER" at 305.181,-32.782 h1.27
  text "REFER" at 322.961,-32.782 h1.27
  text "PACKAGING AND HANDLING:" at 261.62,-32.909 h1.52
  text "X" at 302.514,-33.036 h1.52
Sheet:
  drawing of 1882 lines, arcs and shapes, not listed
  text "1" at 3.717,207.391 h1.78
  text "2" at 52.756,207.391 h1.78
  text "3" at 102.015,207.391 h1.78
  text "4" at 151.308,207.391 h1.78
  text "5" at 200.584,207.391 h1.78
  text "6" at 249.606,207.391 h1.78
  text "7" at 299.136,207.391 h1.78
  text "8" at 348.158,207.391 h1.78
  text "A" at -18.415,173.406 h1.78
  text "A" at 370.205,173.406 h1.78
  text "B" at -18.415,102.794 h1.78
  text "B" at 370.205,102.794 h1.78
  text "C" at -18.415,32.182 h1.78
  text "C" at 370.205,32.182 h1.78
  text "D" at -18.415,-37.922 h1.78
  text "D" at 370.205,-37.922 h1.78
  text "ENGINEER:" at 255.27,-38.1 h1.14
  text "TITLE:" at 293.37,-38.1 h1.14
  text "PCB DESIGNER:" at 255.27,-45.593 h1.14
  text "DATE:" at 255.27,-53.34 h1.14
  text "PART NO.:" at 293.37,-53.34 h1.14
  text "REV:" at 346.71,-53.34 h1.14
  text "Altium Limited" at 222.25,-55.88 h1.78
  text ".PRINT_DATE" at 256.54,-56.388 h1.78
  text "12a Rodborough Rd" at 222.25,-58.42 h1.78
  text "Frenchs Forest" at 222.25,-60.96 h1.78
  text "FILE NAME:" at 255.27,-60.96 h1.14
  text "DWG NO:" at 293.37,-60.96 h1.14
  text "SCALE:" at 346.71,-60.96 h1.14
  text "NSW 2086" at 222.25,-63.5 h1.78
  text ".PCB_FILE_NAME_NO_PATH" at 256.54,-64.008 h1.78
  text "1" at 3.717,-69.469 h1.78
  text "2" at 52.756,-69.469 h1.78
  text "3" at 102.015,-69.469 h1.78
  text "4" at 151.308,-69.469 h1.78
  text "5" at 200.584,-69.469 h1.78
  text "6" at 249.606,-69.469 h1.78
  text "7" at 299.136,-69.469 h1.78
  text "8" at 348.158,-69.469 h1.78
Drill Drawing:
  text ".Legend" at 0,-8 h0.75

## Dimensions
34.5,-69.801 to 34.5,84 on Dimensions
0.001,0.001 to 0.001,77 on Dimensions
0.001,0.001 to 68.999,0.001 on Dimensions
